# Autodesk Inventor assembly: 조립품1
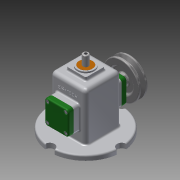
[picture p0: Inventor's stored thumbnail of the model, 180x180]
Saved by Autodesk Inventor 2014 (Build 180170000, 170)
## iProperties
Created: 2018-07
Part Number: 조립품1
Document SubType Name: Assembly
Designer: OA65
Author: OA65
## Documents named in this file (16)
- C:\Users\OA65\Desktop\480708V1001\조립품1.iam
- C:\Users\OA65\Desktop\480708V1001\본체.ipt
- C:\Users\OA65\Desktop\480708V1001\부시.ipt
- C:\Users\OA65\Desktop\480708V1001\뒤커버.ipt
- C:\Users\OA65\Desktop\480708V1001\앞커버.ipt
- C:\Users\OA65\Desktop\480708V1001\베어링 12x32x10.ipt
- C:\Users\OA65\Desktop\480708V1001\편심축.ipt
- C:\Users\OA65\Desktop\480708V1001\오일 실 12 25 7.ipt
- C:\Users\OA65\Desktop\480708V1001\V벨트풀리.ipt
- C:\Users\OA65\Desktop\480708V1001\키 4x4x10.ipt
- C:\Users\OA65\Desktop\480708V1001\멈춤나사 M3x8.ipt
- C:\Users\OA65\Desktop\480708V1001\슬라이드.ipt
- C:\Users\OA65\Desktop\480708V1001\링크.ipt
- C:\Users\OA65\Desktop\480708V1001\고정핀 1.2x8.ipt
- C:\Users\OA65\Desktop\480708V1001\핀 5x18.ipt
- C:\Users\OA65\Desktop\480708V1001\볼트 M4.ipt
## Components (3 placed, 3 different names)
1. V벨트풀리:1
2. 고정핀 1.2x8:1
3. 핀 5x18:1
